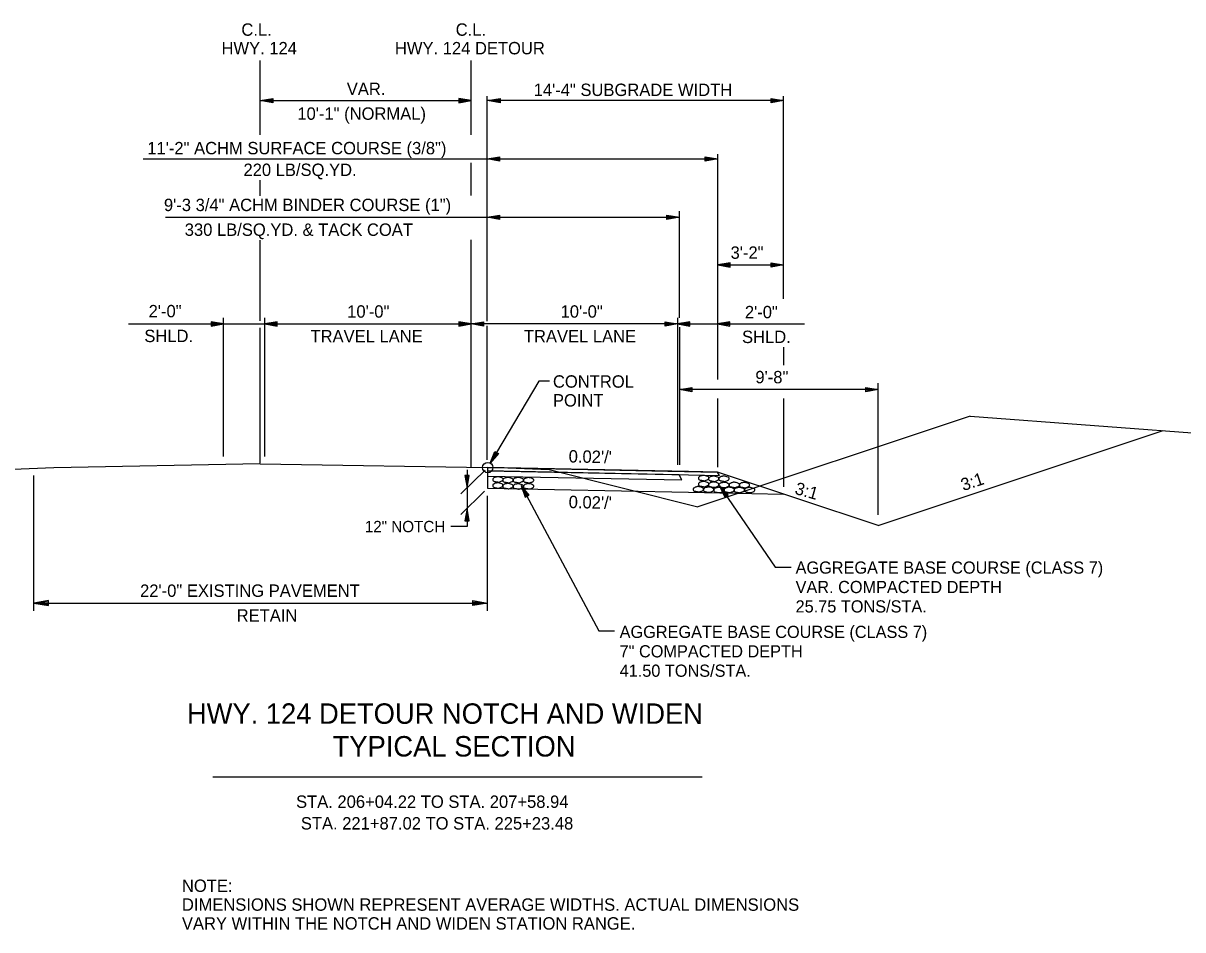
# Model space of a CAD drawing. Extents: x 1824008 to 1828864, y 689441 to 689870.
# Drawn here: x 1828769.2 to 1828825.4, y 689666.2 to 689710.1 of the extents above; entities that cross this region are included whole.
import ezdxf

# ---------------------------------------------------------------- set-up
doc = ezdxf.new("R2010")
doc.units = 0
for name, color, linetype in [('1', 7, 'Continuous'), ('10', 7, 'Continuous'), ('19', 7, 'Continuous'), ('Level 1', 7, 'Continuous'), ('R_Draft', 7, 'Continuous'), ('R_Horz Alg', 7, 'Continuous')]:
    doc.layers.add(name, color=color, linetype=linetype)

# ---------------------------------------------------------------- blocks, each defined once
blk = doc.blocks.new('ROCKS')
at = {"layer": '1'}
blk.add_spline([(0.013, 0.06), (0.053, 0.053), (0.107, 0.033), (0.133, 0.013), (0.133, -0.007), (0.12, -0.033), (0.107, -0.04), (0.073, -0.053), (0.033, -0.067), (0.013, -0.067), (-0.02, -0.06), (-0.06, -0.053), (-0.087, -0.047), (-0.113, -0.02), (-0.113, -0.007), (-0.107, 0.02), (-0.087, 0.033), (-0.067, 0.047), (-0.033, 0.053), (-0.02, 0.06), (0.013, 0.06)], degree=3, dxfattribs=at)

msp = doc.modelspace()

# ---------------------------------------------------------------- linework, layer by layer
at = {"layer": '1'}
for p, q in [((1828780.706, 689706.337), (1828781.306, 689706.442)), ((1828780.706, 689706.337), (1828790.921, 689706.337)), ((1828781.306, 689706.232), (1828780.706, 689706.337)), ((1828780.866, 689706.352), (1828781.306, 689706.387)), ((1828781.306, 689706.282), (1828780.866, 689706.322)), ((1828781.306, 689706.442), (1828781.306, 689706.232)), ((1828790.321, 689706.442), (1828790.321, 689706.232)), ((1828790.921, 689706.337), (1828790.321, 689706.442)), ((1828790.761, 689706.352), (1828790.321, 689706.387)), ((1828790.321, 689706.232), (1828790.921, 689706.337)), ((1828790.321, 689706.282), (1828790.761, 689706.322)), ((1828791.723, 689706.337), (1828792.323, 689706.442)), ((1828792.323, 689706.232), (1828791.723, 689706.337)), ((1828791.883, 689706.352), (1828792.323, 689706.387)), ((1828792.323, 689706.282), (1828791.883, 689706.322)), ((1828792.323, 689706.442), (1828792.323, 689706.232)), ((1828805.457, 689706.232), (1828805.457, 689706.442)), ((1828805.457, 689706.442), (1828806.057, 689706.337)), ((1828805.457, 689706.387), (1828805.897, 689706.352)), ((1828806.057, 689706.337), (1828805.457, 689706.232)), ((1828805.897, 689706.322), (1828805.457, 689706.282)), ((1828791.702, 689703.513), (1828792.302, 689703.618)), ((1828792.302, 689703.408), (1828791.702, 689703.513)), ((1828791.862, 689703.528), (1828792.302, 689703.563)), ((1828792.302, 689703.458), (1828791.862, 689703.498)), ((1828792.302, 689703.618), (1828792.302, 689703.408)), ((1828802.272, 689703.408), (1828802.272, 689703.618)), ((1828802.272, 689703.618), (1828802.872, 689703.513)), ((1828802.272, 689703.563), (1828802.712, 689703.528)), ((1828802.872, 689703.513), (1828802.272, 689703.408)), ((1828802.712, 689703.498), (1828802.272, 689703.458)), ((1828791.702, 689700.688), (1828792.302, 689700.793)), ((1828792.302, 689700.583), (1828791.702, 689700.688)), ((1828791.862, 689700.703), (1828792.302, 689700.738)), ((1828792.302, 689700.633), (1828791.862, 689700.673)), ((1828792.302, 689700.793), (1828792.302, 689700.583)), ((1828800.415, 689700.583), (1828800.415, 689700.793)), ((1828800.415, 689700.793), (1828801.015, 689700.688)), ((1828800.415, 689700.738), (1828800.855, 689700.703)), ((1828801.015, 689700.688), (1828800.415, 689700.583)), ((1828800.855, 689700.673), (1828800.415, 689700.633)), ((1828803.472, 689698.482), (1828802.872, 689698.377)), ((1828802.872, 689698.377), (1828803.472, 689698.272)), ((1828803.472, 689698.427), (1828803.032, 689698.392)), ((1828803.032, 689698.362), (1828803.472, 689698.322)), ((1828803.472, 689698.272), (1828803.472, 689698.482)), ((1828805.457, 689698.272), (1828805.457, 689698.482)), ((1828805.457, 689698.482), (1828806.057, 689698.377)), ((1828805.457, 689698.427), (1828805.897, 689698.392)), ((1828806.057, 689698.377), (1828805.457, 689698.272)), ((1828805.897, 689698.362), (1828805.457, 689698.322)), ((1828778.321, 689695.63), (1828778.321, 689695.42)), ((1828778.921, 689695.525), (1828778.321, 689695.63)), ((1828778.761, 689695.54), (1828778.321, 689695.575)), ((1828778.321, 689695.42), (1828778.921, 689695.525)), ((1828778.321, 689695.47), (1828778.761, 689695.51)), ((1828780.921, 689689.095), (1828780.921, 689695.825)), ((1828781.521, 689695.63), (1828780.921, 689695.525)), ((1828780.921, 689695.525), (1828790.921, 689695.525)), ((1828780.921, 689695.525), (1828781.521, 689695.42)), ((1828781.521, 689695.575), (1828781.081, 689695.54)), ((1828781.081, 689695.51), (1828781.521, 689695.47)), ((1828781.521, 689695.42), (1828781.521, 689695.63)), ((1828790.921, 689695.525), (1828791.521, 689695.63)), ((1828791.521, 689695.42), (1828790.921, 689695.525)), ((1828800.921, 689695.525), (1828790.921, 689695.525)), ((1828800.921, 689695.525), (1828791.06, 689695.525)), ((1828800.921, 689695.525), (1828791.06, 689695.525)), ((1828791.081, 689695.54), (1828791.521, 689695.575)), ((1828791.521, 689695.47), (1828791.081, 689695.51)), ((1828791.521, 689695.63), (1828791.521, 689695.42)), ((1828800.321, 689695.42), (1828800.321, 689695.63)), ((1828800.321, 689695.63), (1828800.921, 689695.525)), ((1828800.321, 689695.575), (1828800.761, 689695.54)), ((1828800.921, 689695.525), (1828800.321, 689695.42)), ((1828800.761, 689695.51), (1828800.321, 689695.47)), ((1828801.521, 689695.63), (1828800.921, 689695.525)), ((1828800.921, 689695.525), (1828801.521, 689695.42)), ((1828801.521, 689695.575), (1828801.081, 689695.54)), ((1828801.081, 689695.51), (1828801.521, 689695.47)), ((1828801.521, 689695.42), (1828801.521, 689695.63)), ((1828803.464, 689695.631), (1828802.864, 689695.526)), ((1828802.864, 689695.526), (1828803.464, 689695.421)), ((1828803.464, 689695.576), (1828803.024, 689695.541)), ((1828803.024, 689695.511), (1828803.464, 689695.471)), ((1828803.464, 689695.421), (1828803.464, 689695.631)), ((1828801.015, 689692.345), (1828801.615, 689692.45)), ((1828810.651, 689692.346), (1828801.015, 689692.345)), ((1828801.615, 689692.24), (1828801.015, 689692.345)), ((1828801.175, 689692.36), (1828801.615, 689692.395)), ((1828801.615, 689692.29), (1828801.175, 689692.33)), ((1828801.615, 689692.45), (1828801.615, 689692.24)), ((1828810.051, 689692.241), (1828810.051, 689692.451)), ((1828810.051, 689692.451), (1828810.651, 689692.346)), ((1828810.051, 689692.396), (1828810.491, 689692.361)), ((1828810.651, 689692.346), (1828810.051, 689692.241)), ((1828810.491, 689692.331), (1828810.051, 689692.291)), ((1828815.101, 689691.061), (1828801.917, 689686.667)), ((1828810.651, 689685.751), (1828824.462, 689690.355)), ((1828780.706, 689688.75), (1828770.706, 689688.55)), ((1828780.706, 689688.75), (1828792.706, 689688.55)), ((1828770.706, 689688.55), (1828768.706, 689688.47)), ((1828769.723, 689681.627), (1828769.723, 689688.179)), ((1828791.598, 689688.442), (1828790.423, 689687.292)), ((1828790.828, 689688.185), (1828790.618, 689688.185)), ((1828790.618, 689688.185), (1828790.723, 689687.585)), ((1828790.673, 689688.185), (1828790.708, 689687.745)), ((1828790.723, 689687.585), (1828790.828, 689688.185)), ((1828790.738, 689687.745), (1828790.778, 689688.185)), ((1828791.723, 689688.569), (1828791.723, 689687.564)), ((1828792.706, 689688.55), (1828800.46, 689688.395)), ((1828792.706, 689688.55), (1828794.706, 689688.47)), ((1828794.706, 689688.47), (1828801.917, 689686.667)), ((1828800.46, 689688.395), (1828802.868, 689688.346)), ((1828810.651, 689685.751), (1828802.866, 689688.346)), ((1828791.723, 689687.569), (1828801.461, 689687.375)), ((1828791.573, 689687.417), (1828790.423, 689686.292)), ((1828791.723, 689681.627), (1828791.723, 689687.19)), ((1828801.461, 689687.375), (1828806.057, 689687.283)), ((1828790.723, 689686.585), (1828790.618, 689685.985)), ((1828790.708, 689686.425), (1828790.668, 689685.985)), ((1828790.828, 689685.985), (1828790.723, 689686.585)), ((1828790.773, 689685.985), (1828790.738, 689686.425)), ((1828790.618, 689685.985), (1828790.828, 689685.985)), ((1828770.438, 689682.127), (1828769.723, 689682.002)), ((1828769.723, 689682.002), (1828791.723, 689682.002)), ((1828769.723, 689682.002), (1828770.438, 689681.876)), ((1828770.438, 689682.061), (1828769.913, 689682.019)), ((1828769.913, 689681.984), (1828770.438, 689681.936)), ((1828770.438, 689681.876), (1828770.438, 689682.127)), ((1828791.007, 689681.876), (1828791.007, 689682.127)), ((1828791.007, 689682.127), (1828791.723, 689682.002)), ((1828791.007, 689682.061), (1828791.532, 689682.019)), ((1828791.723, 689682.002), (1828791.007, 689681.876)), ((1828791.532, 689681.984), (1828791.007, 689681.936)), ((1828778.408, 689673.582), (1828802.12, 689673.582))]:
    msp.add_line(p, q, dxfattribs=at)
for points in [[(1828815.101, 689691.061), (1828827.154, 689690.152), (1828838.209, 689688.991), (1828849.374, 689686.966), (1828855.735, 689686.83)], [(1828790.723, 689688.457), (1828790.723, 689685.708), (1828789.946, 689685.708)]]:
    msp.add_lwpolyline(points, dxfattribs=at)
msp.add_circle((1828791.727, 689688.564), 0.25, dxfattribs=at)
at = {"layer": '19'}
for p, q in [((1828791.702, 689701.347), (1828791.702, 689706.562)), ((1828806.057, 689706.337), (1828791.723, 689706.337)), ((1828806.057, 689696.736), (1828806.057, 689706.562)), ((1828775.034, 689703.513), (1828791.702, 689703.513)), ((1828791.702, 689695.656), (1828791.702, 689703.738)), ((1828791.702, 689703.513), (1828802.872, 689703.513)), ((1828802.872, 689692.826), (1828802.872, 689703.738)), ((1828776.106, 689700.688), (1828791.702, 689700.688)), ((1828791.702, 689695.825), (1828791.702, 689700.988)), ((1828791.702, 689700.688), (1828801.015, 689700.688)), ((1828801.015, 689695.825), (1828801.015, 689700.988)), ((1828778.921, 689689.095), (1828778.921, 689695.825)), ((1828800.921, 689695.825), (1828800.921, 689688.694)), ((1828801.015, 689695.373), (1828801.015, 689688.694)), ((1828806.057, 689694.399), (1828806.057, 689693.518)), ((1828802.872, 689688.58), (1828802.872, 689691.916)), ((1828806.057, 689691.916), (1828806.057, 689687.634)), ((1828801.461, 689688.375), (1828791.723, 689688.569)), ((1828791.723, 689688.569), (1828791.723, 689688.569)), ((1828791.723, 689688.569), (1828791.723, 689688.569)), ((1828791.723, 689688.569), (1828791.723, 689688.569)), ((1828791.723, 689688.569), (1828791.723, 689688.569)), ((1828791.723, 689688.569), (1828791.723, 689688.403)), ((1828791.723, 689688.403), (1828801.458, 689688.208)), ((1828791.723, 689688.403), (1828791.723, 689688.403)), ((1828791.723, 689688.403), (1828791.723, 689688.403)), ((1828791.723, 689688.403), (1828791.723, 689688.403)), ((1828801.003, 689688.217), (1828791.723, 689688.403)), ((1828791.723, 689688.153), (1828791.723, 689688.153)), ((1828791.723, 689688.153), (1828791.723, 689688.153)), ((1828791.723, 689688.153), (1828801.127, 689687.965)), ((1828801.127, 689687.965), (1828801.003, 689688.217)), ((1828801.458, 689688.208), (1828802.952, 689688.178)), ((1828802.866, 689688.346), (1828801.461, 689688.375)), ((1828802.952, 689688.178), (1828802.866, 689688.346)), ((1828793.34, 689687.699), (1828797.112, 689680.65)), ((1828793.729, 689687.23), (1828793.34, 689687.699)), ((1828793.34, 689687.699), (1828793.546, 689687.126)), ((1828793.406, 689687.553), (1828793.59, 689687.151)), ((1828793.681, 689687.203), (1828793.432, 689687.568)), ((1828802.96, 689687.679), (1828805.661, 689683.745)), ((1828803.385, 689687.243), (1828802.96, 689687.679)), ((1828802.96, 689687.679), (1828803.212, 689687.124)), ((1828803.038, 689687.538), (1828803.253, 689687.152)), ((1828803.34, 689687.212), (1828803.062, 689687.555)), ((1828793.546, 689687.126), (1828793.729, 689687.23)), ((1828803.212, 689687.124), (1828803.385, 689687.243)), ((1828805.661, 689683.745), (1828806.427, 689683.745)), ((1828797.112, 689680.65), (1828797.878, 689680.65))]:
    msp.add_line(p, q, dxfattribs=at)
for points in [[(1828791.723, 689688.403), (1828791.723, 689688.153)], [(1828791.723, 689688.153), (1828791.723, 689688.153)]]:
    msp.add_lwpolyline(points, dxfattribs=at)
at = {"layer": 'R_Draft'}
for p, q in [((1828780.706, 689704.677), (1828780.706, 689708.281)), ((1828790.921, 689704.677), (1828790.921, 689708.281)), ((1828790.921, 689701.736), (1828790.921, 689703.319)), ((1828780.706, 689701.727), (1828780.706, 689702.491)), ((1828780.706, 689695.666), (1828780.706, 689699.582)), ((1828790.921, 689697.297), (1828790.921, 689699.596)), ((1828802.872, 689698.377), (1828806.057, 689698.377)), ((1828790.921, 689688.595), (1828790.921, 689697.297)), ((1828774.316, 689695.525), (1828780.921, 689695.525)), ((1828790.321, 689695.63), (1828790.321, 689695.42)), ((1828790.921, 689695.525), (1828790.321, 689695.63)), ((1828790.761, 689695.54), (1828790.321, 689695.575)), ((1828790.321, 689695.42), (1828790.921, 689695.525)), ((1828790.321, 689695.47), (1828790.761, 689695.51)), ((1828800.921, 689695.525), (1828807.082, 689695.525)), ((1828780.706, 689688.77), (1828780.706, 689695.337)), ((1828791.85, 689688.782), (1828792.065, 689689.351)), ((1828792.244, 689689.245), (1828791.85, 689688.782)), ((1828791.922, 689688.924), (1828792.109, 689689.32)), ((1828792.203, 689689.265), (1828791.945, 689688.913)), ((1828792.065, 689689.351), (1828792.244, 689689.245))]:
    msp.add_line(p, q, dxfattribs=at)
msp.add_lwpolyline([(1828794.728, 689692.757), (1828794.197, 689692.757), (1828791.85, 689688.782)], dxfattribs=at)
at = {"layer": 'R_Horz Alg'}
for p, q in [((1828791.702, 689688.941), (1828791.702, 689695.431)), ((1828810.651, 689686.268), (1828810.651, 689692.646))]:
    msp.add_line(p, q, dxfattribs=at)

# ---------------------------------------------------------------- block references
at = {"layer": 'Level 1', "xscale": 2.0116542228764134, "yscale": 2.0116542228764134, "rotation": 0.3302009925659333}
for p in [(1828792.202, 689687.995), (1828792.688, 689687.963), (1828793.188, 689687.963), (1828793.691, 689687.958), (1828802.173, 689688.063), (1828802.66, 689688.031), (1828803.16, 689688.031), (1828792.197, 689687.703), (1828792.688, 689687.676), (1828793.184, 689687.659), (1828793.687, 689687.664), (1828801.916, 689687.521), (1828802.169, 689687.771), (1828802.412, 689687.501), (1828802.66, 689687.744), (1828802.908, 689687.484), (1828803.156, 689687.727), (1828803.411, 689687.49), (1828803.659, 689687.732), (1828803.902, 689687.481), (1828804.15, 689687.724), (1828804.403, 689687.484)]:
    msp.add_blockref('ROCKS', p, dxfattribs=at)

# ---------------------------------------------------------------- texts
at = {"layer": '1'}
for s, height, rotation, p in [('C.L.', 0.6, 360, (1828779.788, 689709.48)), ('C.L.', 0.6, 360, (1828790.175, 689709.48)), ('HWY. 124', 0.6, 360, (1828778.825, 689708.58)), ('HWY. 124 DETOUR', 0.6, 360, (1828787.229, 689708.58)), ("0.02'/'", 0.6, 358.8542, (1828795.646, 689688.815)), ("0.02'/'", 0.6, 358.8542, (1828795.646, 689688.815)), ('3:1', 0.6, 18.4349, (1828814.775, 689687.423)), ('3:1', 0.6, 344.2251, (1828806.571, 689687.297)), ("0.02'/'", 0.6, 358.8542, (1828795.646, 689686.604)), ('HWY. 124 DETOUR NOTCH AND WIDEN', 0.98999, 359.9954, (1828777.151, 689676.154)), ('TYPICAL SECTION ', 0.98999, 359.9954, (1828784.213, 689674.569))]:
    msp.add_text(s, height=height, rotation=rotation, dxfattribs=at).set_placement(p)
for s, p in [('VAR.', (1828784.897, 689706.61)), ('14\'-4" SUBGRADE WIDTH', (1828793.954, 689706.562)), ('10\'-1" (NORMAL)', (1828782.501, 689705.41)), ('11\'-2" ACHM SURFACE COURSE (3/8")', (1828775.228, 689703.738)), ('220 LB/SQ.YD.', (1828779.89, 689702.688)), ('9\'-3 3/4" ACHM BINDER COURSE (1")', (1828776.035, 689700.988)), ('330 LB/SQ.YD. & TACK COAT', (1828777.044, 689699.788)), ('SHLD.', (1828804.052, 689694.596)), ('22\'-0" EXISTING PAVEMENT', (1828774.879, 689682.302)), ('RETAIN', (1828779.56, 689681.102))]:
    msp.add_text(s, height=0.6, dxfattribs=at).set_placement(p)
at = {"layer": '10'}
msp.add_text('12" NOTCH', height=0.55, dxfattribs=at).set_placement((1828785.771, 689685.433))
at = {"layer": '19'}
for s, p in [('AGGREGATE BASE COURSE (CLASS 7)', (1828806.648, 689683.425)), ('VAR. COMPACTED DEPTH', (1828806.648, 689682.485)), ('25.75 TONS/STA.', (1828806.648, 689681.545)), ('AGGREGATE BASE COURSE (CLASS 7)', (1828798.12, 689680.311)), ('7" COMPACTED DEPTH', (1828798.12, 689679.371)), ('41.50 TONS/STA.', (1828798.12, 689678.431))]:
    msp.add_text(s, height=0.59001, rotation=360, dxfattribs=at).set_placement(p)
at = {"layer": 'R_Draft'}
for s, p in [('3\'-2"', (1828803.497, 689698.677)), ('10\'-0"', (1828795.258, 689695.825)), ('2\'-0"', (1828804.19, 689695.796)), ('TRAVEL LANE', (1828793.479, 689694.625)), ('9\'-8"', (1828804.699, 689692.646))]:
    msp.add_text(s, height=0.6, dxfattribs=at).set_placement(p)
for s, rotation, p in [('2\'-0"', 360, (1828775.293, 689695.842)), ('10\'-0"', 360, (1828784.917, 689695.825)), ('SHLD.', 360, (1828775.085, 689694.642)), ('TRAVEL LANE', 360, (1828783.138, 689694.625)), ('CONTROL', 360, (1828794.888, 689692.434)), ('POINT', 360, (1828794.888, 689691.522)), ('STA. 206+04.22 TO STA. 207+58.94', 359.9954, (1828782.438, 689672.082)), ('STA. 221+87.02 TO STA. 225+23.48', 359.9954, (1828782.67, 689671.034)), ('NOTE:', 359.9954, (1828776.907, 689668.011)), ('DIMENSIONS SHOWN REPRESENT AVERAGE WIDTHS. ACTUAL DIMENSIONS', 359.9954, (1828776.907, 689667.099)), ('VARY WITHIN THE NOTCH AND WIDEN STATION RANGE.', 359.9954, (1828776.907, 689666.186))]:
    msp.add_text(s, height=0.6, rotation=rotation, dxfattribs=at).set_placement(p)

doc.saveas('drawing.dxf')
